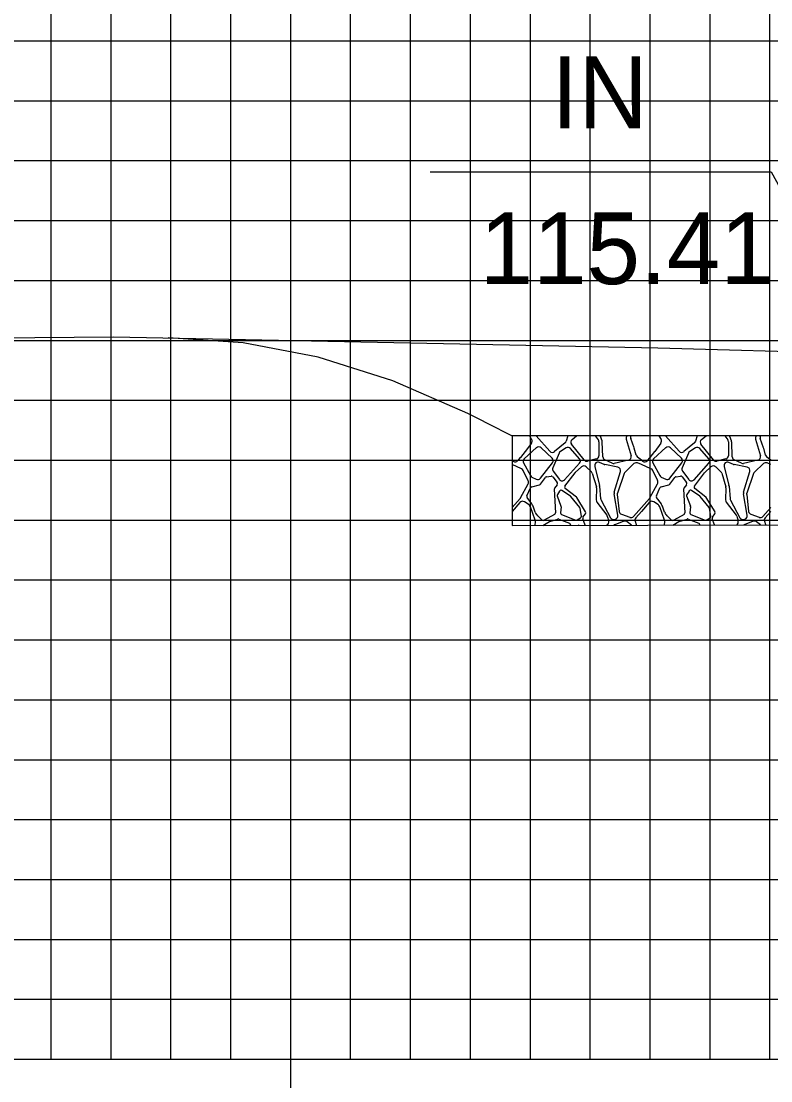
# Model space of a CAD drawing. Extents: x 1771629 to 1771972, y 442591 to 442811.
# Drawn here: x 1771740.08 to 1771752.59, y 442608.3 to 442625.99 of the extents above; entities that cross this region are included whole.
import ezdxf

# ---------------------------------------------------------------- set-up
doc = ezdxf.new("R2010")
doc.units = 0
for name, color, linetype in [('ANNOTATION', 7, 'Continuous'), ('D_Roadway_SlopeLines', 7, 'Continuous'), ('MAJOR', 7, 'Continuous'), ('MINOR', 7, 'Continuous'), ('S_Roadway_Centerline', 7, 'Continuous')]:
    doc.layers.add(name, color=color, linetype=linetype)

msp = doc.modelspace()

# ---------------------------------------------------------------- linework, layer by layer
at = {"layer": 'ANNOTATION'}
msp.add_lwpolyline([(1771746.908, 442623.478), (1771752.6, 442623.478), (1771755.024, 442619.074)], dxfattribs=at)
at = {"layer": 'D_Roadway_SlopeLines'}
for p, q in [((1771748.076, 442619.173), (1771748.274, 442619.074)), ((1771748.599, 442618.95), (1771748.496, 442618.811)), ((1771748.566, 442619.074), (1771748.602, 442619.012)), ((1771748.906, 442618.814), (1771748.678, 442619.074)), ((1771749.162, 442618.956), (1771748.985, 442618.808)), ((1771749.204, 442619.074), (1771749.18, 442618.985)), ((1771749.477, 442618.669), (1771749.269, 442618.932)), ((1771749.277, 442619.011), (1771749.353, 442619.074)), ((1771749.665, 442619.074), (1771749.715, 442619.006)), ((1771749.726, 442618.973), (1771749.726, 442618.74)), ((1771749.777, 442618.988), (1771749.753, 442619.058)), ((1771749.791, 442618.719), (1771749.78, 442618.971)), ((1771750.189, 442619.074), (1771750.181, 442619.046)), ((1771750.181, 442619.015), (1771750.261, 442618.736)), ((1771750.255, 442619.058), (1771750.258, 442619.074)), ((1771750.315, 442618.869), (1771750.257, 442619.029)), ((1771750.759, 442618.95), (1771750.656, 442618.811)), ((1771750.726, 442619.074), (1771750.762, 442619.012)), ((1771751.066, 442618.814), (1771750.838, 442619.074)), ((1771751.322, 442618.956), (1771751.145, 442618.808)), ((1771751.364, 442619.074), (1771751.34, 442618.985)), ((1771751.637, 442618.669), (1771751.429, 442618.932)), ((1771751.437, 442619.011), (1771751.513, 442619.074)), ((1771751.825, 442619.074), (1771751.875, 442619.006)), ((1771751.886, 442618.973), (1771751.886, 442618.74)), ((1771751.937, 442618.988), (1771751.913, 442619.058)), ((1771751.951, 442618.719), (1771751.941, 442618.971)), ((1771752.349, 442619.074), (1771752.341, 442619.046)), ((1771752.341, 442619.015), (1771752.421, 442618.736)), ((1771752.415, 442619.058), (1771752.418, 442619.074)), ((1771752.475, 442618.869), (1771752.418, 442619.029)), ((1771748.495, 442618.809), (1771748.414, 442618.709)), ((1771748.683, 442618.874), (1771748.477, 442618.689)), ((1771748.943, 442618.698), (1771748.76, 442618.872)), ((1771749.059, 442618.782), (1771748.955, 442618.538)), ((1771749.177, 442618.87), (1771749.081, 442618.808)), ((1771749.401, 442618.688), (1771749.251, 442618.86)), ((1771750.348, 442618.746), (1771750.316, 442618.864)), ((1771750.655, 442618.809), (1771750.574, 442618.709)), ((1771750.843, 442618.874), (1771750.637, 442618.689)), ((1771751.103, 442618.698), (1771750.92, 442618.872)), ((1771751.219, 442618.782), (1771751.115, 442618.538)), ((1771751.337, 442618.87), (1771751.241, 442618.808)), ((1771751.561, 442618.688), (1771751.411, 442618.86)), ((1771752.508, 442618.746), (1771752.476, 442618.864)), ((1771748.293, 442618.649), (1771748.274, 442618.665)), ((1771748.434, 442618.522), (1771748.274, 442618.591)), ((1771748.413, 442618.709), (1771748.373, 442618.659)), ((1771748.465, 442618.619), (1771748.581, 442618.407)), ((1771748.751, 442618.362), (1771748.949, 442618.622)), ((1771749.153, 442618.339), (1771749.4, 442618.613)), ((1771749.682, 442618.685), (1771749.535, 442618.649)), ((1771749.813, 442618.595), (1771749.733, 442618.628)), ((1771750.04, 442618.548), (1771749.823, 442618.591)), ((1771749.946, 442618.616), (1771749.825, 442618.67)), ((1771750.218, 442618.665), (1771749.981, 442618.612)), ((1771750.309, 442618.607), (1771750.162, 442618.467)), ((1771750.434, 442618.665), (1771750.368, 442618.716)), ((1771750.434, 442618.591), (1771750.371, 442618.618)), ((1771750.454, 442618.649), (1771750.434, 442618.665)), ((1771750.594, 442618.522), (1771750.434, 442618.591)), ((1771750.573, 442618.709), (1771750.533, 442618.659)), ((1771750.625, 442618.619), (1771750.741, 442618.407)), ((1771750.911, 442618.362), (1771751.109, 442618.622)), ((1771751.313, 442618.339), (1771751.561, 442618.613)), ((1771751.842, 442618.685), (1771751.695, 442618.649)), ((1771751.973, 442618.595), (1771751.893, 442618.628)), ((1771752.2, 442618.548), (1771751.983, 442618.591)), ((1771752.106, 442618.616), (1771751.985, 442618.67)), ((1771752.379, 442618.665), (1771752.141, 442618.612)), ((1771752.47, 442618.607), (1771752.322, 442618.467)), ((1771752.594, 442618.665), (1771752.528, 442618.716)), ((1771752.594, 442618.591), (1771752.531, 442618.618)), ((1771748.546, 442618.32), (1771748.463, 442618.494)), ((1771748.852, 442618.388), (1771748.926, 442618.4)), ((1771748.953, 442618.389), (1771749.028, 442618.29)), ((1771748.962, 442618.481), (1771749.065, 442618.343)), ((1771749.158, 442618.231), (1771749.328, 442618.453)), ((1771749.331, 442618.457), (1771749.435, 442618.553)), ((1771749.513, 442618.553), (1771749.599, 442618.471)), ((1771749.614, 442618.446), (1771749.683, 442618.22)), ((1771749.656, 442618.561), (1771749.735, 442618.241)), ((1771749.979, 442618.13), (1771750.083, 442618.476)), ((1771750.147, 442618.444), (1771750.034, 442618.117)), ((1771750.706, 442618.32), (1771750.623, 442618.494)), ((1771751.012, 442618.388), (1771751.086, 442618.4)), ((1771751.113, 442618.389), (1771751.188, 442618.29)), ((1771751.122, 442618.481), (1771751.225, 442618.343)), ((1771751.318, 442618.231), (1771751.488, 442618.453)), ((1771751.491, 442618.457), (1771751.595, 442618.553)), ((1771751.674, 442618.553), (1771751.759, 442618.471)), ((1771751.775, 442618.446), (1771751.843, 442618.22)), ((1771751.816, 442618.561), (1771751.895, 442618.241)), ((1771752.139, 442618.13), (1771752.243, 442618.476)), ((1771752.307, 442618.444), (1771752.194, 442618.117)), ((1771748.417, 442618.035), (1771748.544, 442618.268)), ((1771748.603, 442618.221), (1771748.734, 442618.253)), ((1771748.606, 442618.383), (1771748.68, 442618.346)), ((1771748.75, 442618.264), (1771748.833, 442618.377)), ((1771749.028, 442618.256), (1771748.985, 442618.199)), ((1771749.736, 442618.232), (1771749.754, 442618.022)), ((1771750.577, 442618.035), (1771750.704, 442618.268)), ((1771750.764, 442618.221), (1771750.894, 442618.253)), ((1771750.766, 442618.383), (1771750.84, 442618.346)), ((1771750.91, 442618.264), (1771750.993, 442618.377)), ((1771751.188, 442618.256), (1771751.145, 442618.199)), ((1771751.897, 442618.232), (1771751.914, 442618.022)), ((1771748.524, 442618.069), (1771748.584, 442618.205)), ((1771748.606, 442617.935), (1771748.527, 442618.041)), ((1771748.979, 442618.181), (1771749, 442617.787)), ((1771749.028, 442618.069), (1771749.091, 442617.9)), ((1771749.068, 442618.15), (1771749.031, 442618.094)), ((1771749.251, 442618.063), (1771749.108, 442618.158)), ((1771749.351, 442618.048), (1771749.163, 442618.191)), ((1771749.404, 442617.874), (1771749.257, 442618.057)), ((1771749.503, 442617.803), (1771749.358, 442618.04)), ((1771749.685, 442618.202), (1771749.68, 442618.002)), ((1771750.042, 442617.746), (1771749.978, 442618.104)), ((1771750.031, 442618.092), (1771750.064, 442617.809)), ((1771750.684, 442618.069), (1771750.744, 442618.205)), ((1771750.767, 442617.935), (1771750.687, 442618.041)), ((1771751.139, 442618.181), (1771751.16, 442617.787)), ((1771751.188, 442618.069), (1771751.251, 442617.9)), ((1771751.229, 442618.15), (1771751.191, 442618.094)), ((1771751.411, 442618.063), (1771751.268, 442618.158)), ((1771751.511, 442618.048), (1771751.324, 442618.191)), ((1771751.564, 442617.874), (1771751.417, 442618.057)), ((1771751.663, 442617.803), (1771751.518, 442618.04)), ((1771751.845, 442618.202), (1771751.84, 442618.002)), ((1771752.202, 442617.746), (1771752.138, 442618.104)), ((1771752.192, 442618.092), (1771752.224, 442617.809)), ((1771748.274, 442617.873), (1771748.409, 442618.024)), ((1771748.406, 442617.96), (1771748.274, 442617.809)), ((1771748.559, 442617.917), (1771748.48, 442617.969)), ((1771748.661, 442617.665), (1771748.58, 442617.889)), ((1771748.662, 442617.797), (1771748.627, 442617.896)), ((1771749.093, 442617.887), (1771749.083, 442617.786)), ((1771749.433, 442617.73), (1771749.41, 442617.861)), ((1771749.691, 442617.966), (1771749.856, 442617.747)), ((1771749.76, 442618), (1771749.916, 442617.704)), ((1771750.303, 442617.726), (1771750.434, 442617.873)), ((1771750.434, 442617.873), (1771750.569, 442618.024)), ((1771750.566, 442617.96), (1771750.434, 442617.809)), ((1771750.719, 442617.917), (1771750.641, 442617.969)), ((1771750.822, 442617.665), (1771750.741, 442617.889)), ((1771750.822, 442617.797), (1771750.787, 442617.896)), ((1771751.253, 442617.887), (1771751.243, 442617.786)), ((1771751.593, 442617.73), (1771751.57, 442617.861)), ((1771751.851, 442617.966), (1771752.016, 442617.747)), ((1771751.92, 442618), (1771752.076, 442617.704)), ((1771752.464, 442617.726), (1771752.594, 442617.873)), ((1771748.779, 442617.665), (1771748.7, 442617.739)), ((1771748.986, 442617.76), (1771748.813, 442617.661)), ((1771748.905, 442617.643), (1771749.037, 442617.683)), ((1771749.056, 442617.682), (1771749.233, 442617.611)), ((1771749.101, 442617.757), (1771749.339, 442617.665)), ((1771749.364, 442617.668), (1771749.42, 442617.701)), ((1771749.496, 442617.578), (1771749.455, 442617.684)), ((1771749.458, 442617.711), (1771749.501, 442617.771)), ((1771749.865, 442617.73), (1771749.89, 442617.65)), ((1771749.982, 442617.676), (1771750.001, 442617.681)), ((1771750.101, 442617.762), (1771750.241, 442617.711)), ((1771750.434, 442617.809), (1771750.339, 442617.7)), ((1771750.939, 442617.665), (1771750.86, 442617.739)), ((1771751.146, 442617.76), (1771750.973, 442617.661)), ((1771751.065, 442617.643), (1771751.197, 442617.683)), ((1771751.216, 442617.682), (1771751.393, 442617.611)), ((1771751.261, 442617.757), (1771751.499, 442617.665)), ((1771751.524, 442617.668), (1771751.58, 442617.701)), ((1771751.654, 442617.584), (1771751.615, 442617.684)), ((1771751.619, 442617.711), (1771751.662, 442617.771)), ((1771752.025, 442617.73), (1771752.05, 442617.65)), ((1771752.142, 442617.676), (1771752.161, 442617.681)), ((1771752.261, 442617.762), (1771752.402, 442617.711)), ((1771752.594, 442617.809), (1771752.499, 442617.7)), ((1771748.661, 442617.575), (1771748.665, 442617.643)), ((1771748.789, 442617.576), (1771748.899, 442617.64)), ((1771749.25, 442617.584), (1771749.25, 442617.577)), ((1771749.854, 442617.579), (1771749.853, 442617.579)), ((1771750.141, 442617.646), (1771749.989, 442617.588)), ((1771750.271, 442617.58), (1771750.196, 442617.638)), ((1771750.328, 442617.646), (1771750.344, 442617.592)), ((1771750.821, 442617.581), (1771750.825, 442617.643)), ((1771750.96, 442617.582), (1771751.059, 442617.64)), ((1771751.411, 442617.584), (1771751.411, 442617.583)), ((1771752.301, 442617.646), (1771752.149, 442617.588)), ((1771752.423, 442617.586), (1771752.356, 442617.638)), ((1771752.488, 442617.646), (1771752.504, 442617.592))]:
    msp.add_line(p, q, dxfattribs=at)
for points in [[(1771748.076, 442619.173), (1771747.536, 442619.443), (1771746.286, 442619.991), (1771745.036, 442620.384), (1771743.786, 442620.622), (1771742.536, 442620.706)], [(1771755.024, 442619.074), (1771748.274, 442619.074), (1771748.274, 442617.574), (1771755.074, 442617.594)]]:
    msp.add_lwpolyline(points, dxfattribs=at)
for centre, radius, start, end in [((1771748.553, 442618.983), 0.057, 323.4711, 30.6507), ((1771749.125, 442618.999), 0.057, 309.9575, 345.2564), ((1771749.313, 442618.967), 0.057, 129.4712, 218.373), ((1771749.669, 442618.973), 0.057, 0.0888, 36.2192), ((1771749.806, 442619.077), 0.057, 182.6788, 199.44), ((1771749.723, 442618.969), 0.057, 2.4366, 19.44), ((1771750.236, 442619.03), 0.057, 164.0546, 195.9454), ((1771750.311, 442619.048), 0.057, 170.1342, 199.6538), ((1771750.713, 442618.983), 0.057, 323.4711, 30.6507), ((1771751.285, 442618.999), 0.057, 309.9575, 345.2564), ((1771751.473, 442618.967), 0.057, 129.4712, 218.373), ((1771751.829, 442618.973), 0.057, 0.0888, 36.2192), ((1771751.967, 442619.077), 0.057, 182.6788, 199.44), ((1771751.884, 442618.969), 0.057, 2.4366, 19.44), ((1771752.396, 442619.03), 0.057, 164.0546, 195.9454), ((1771752.471, 442619.048), 0.057, 170.1342, 199.6538), ((1771748.45, 442618.845), 0.057, 320.9061, 323.4711), ((1771748.721, 442618.831), 0.057, 46.4321, 131.8334), ((1771748.949, 442618.852), 0.057, 221.257, 309.9575), ((1771749.112, 442618.76), 0.057, 122.9625, 156.9778), ((1771749.208, 442618.822), 0.057, 41.2462, 122.9625), ((1771749.669, 442618.74), 0.057, 283.5819, 0.0888), ((1771750.261, 442618.849), 0.057, 15.2551, 19.6538), ((1771750.403, 442618.761), 0.057, 195.2551, 231.953), ((1771750.61, 442618.845), 0.057, 320.9061, 323.4711), ((1771750.881, 442618.831), 0.057, 46.4321, 131.8334), ((1771751.109, 442618.852), 0.057, 221.257, 309.9575), ((1771751.272, 442618.76), 0.057, 122.9625, 156.9778), ((1771751.368, 442618.822), 0.057, 41.2462, 122.9625), ((1771751.829, 442618.74), 0.057, 283.5819, 0.0888), ((1771752.421, 442618.849), 0.057, 15.2551, 19.6538), ((1771752.563, 442618.761), 0.057, 195.2551, 231.953), ((1771748.329, 442618.694), 0.057, 231.953, 321.3402), ((1771748.458, 442618.673), 0.057, 140.9061, 141.3402), ((1771748.515, 442618.646), 0.057, 131.8334, 208.7575), ((1771748.904, 442618.657), 0.057, 322.6367, 46.4321), ((1771749.358, 442618.651), 0.057, 317.8776, 41.2462), ((1771749.474, 442618.511), 0.057, 46.3639, 132.7891), ((1771749.521, 442618.704), 0.057, 218.373, 283.5819), ((1771749.711, 442618.575), 0.057, 67.4775, 193.8595), ((1771749.848, 442618.722), 0.057, 182.4366, 246.0375), ((1771749.834, 442618.647), 0.057, 247.4775, 258.7067), ((1771749.969, 442618.668), 0.057, 246.0375, 282.4074), ((1771750.206, 442618.72), 0.057, 282.4074, 15.9454), ((1771750.349, 442618.566), 0.057, 66.6444, 133.5732), ((1771750.489, 442618.694), 0.057, 231.953, 321.3402), ((1771750.618, 442618.673), 0.057, 140.9061, 141.3402), ((1771750.675, 442618.646), 0.057, 131.8334, 208.7575), ((1771751.064, 442618.657), 0.057, 322.6367, 46.4321), ((1771751.518, 442618.651), 0.057, 317.8776, 41.2462), ((1771751.634, 442618.511), 0.057, 46.3639, 132.7891), ((1771751.682, 442618.704), 0.057, 218.373, 283.5819), ((1771751.871, 442618.575), 0.057, 67.4775, 193.8595), ((1771752.008, 442618.722), 0.057, 182.4366, 246.0375), ((1771751.995, 442618.647), 0.057, 247.4775, 258.7067), ((1771752.129, 442618.668), 0.057, 246.0375, 282.4074), ((1771752.366, 442618.72), 0.057, 282.4074, 15.9454), ((1771752.509, 442618.566), 0.057, 66.6444, 133.5732), ((1771748.411, 442618.47), 0.057, 25.4039, 66.6444), ((1771748.631, 442618.434), 0.057, 208.7575, 243.4931), ((1771748.856, 442618.36), 0.0285, 98.7462, 143.6864), ((1771748.93, 442618.371), 0.0285, 37.5348, 98.7462), ((1771749.008, 442618.515), 0.057, 156.9778, 216.6071), ((1771749.351, 442618.436), 0.0285, 132.7891, 142.5946), ((1771749.56, 442618.429), 0.057, 16.8986, 46.3639), ((1771750.029, 442618.492), 0.057, 343.267, 78.7067), ((1771750.201, 442618.425), 0.057, 133.5732, 160.9362), ((1771750.572, 442618.47), 0.057, 25.4039, 66.6444), ((1771750.791, 442618.434), 0.057, 208.7575, 243.4931), ((1771751.016, 442618.36), 0.0285, 98.7462, 143.6864), ((1771751.09, 442618.371), 0.0285, 37.5348, 98.7462), ((1771751.168, 442618.515), 0.057, 156.9778, 216.6071), ((1771751.511, 442618.436), 0.0285, 132.7891, 142.5946), ((1771751.72, 442618.429), 0.057, 16.8986, 46.3639), ((1771752.189, 442618.492), 0.057, 343.267, 78.7067), ((1771752.361, 442618.425), 0.057, 133.5732, 160.9362), ((1771748.494, 442618.295), 0.057, 331.294, 25.4039), ((1771748.61, 442618.194), 0.0285, 103.7608, 156.1398), ((1771748.705, 442618.397), 0.057, 243.4931, 322.6367), ((1771748.727, 442618.281), 0.0285, 283.7608, 323.6864), ((1771749.006, 442618.273), 0.0285, 322.4314, 37.5348), ((1771749.111, 442618.377), 0.057, 216.6071, 317.8776), ((1771749.181, 442618.214), 0.0285, 142.5946, 232.5946), ((1771749.628, 442618.204), 0.057, 358.4306, 16.8986), ((1771749.68, 442618.228), 0.057, 4.7636, 13.8595), ((1771750.654, 442618.295), 0.057, 331.294, 25.4039), ((1771750.77, 442618.194), 0.0285, 103.7608, 156.1398), ((1771750.865, 442618.397), 0.057, 243.4931, 322.6367), ((1771750.887, 442618.281), 0.0285, 283.7608, 323.6864), ((1771751.166, 442618.273), 0.0285, 322.4314, 37.5348), ((1771751.271, 442618.377), 0.057, 216.6071, 317.8776), ((1771751.341, 442618.214), 0.0285, 142.5946, 232.5946), ((1771751.789, 442618.204), 0.057, 358.4306, 16.8986), ((1771751.84, 442618.228), 0.057, 4.7636, 13.8595), ((1771748.367, 442618.062), 0.057, 318.2412, 331.294), ((1771748.55, 442618.058), 0.0285, 156.1398, 216.7644), ((1771749.008, 442618.182), 0.0285, 142.4314, 182.9903), ((1771749.055, 442618.079), 0.0285, 146.3099, 200.4835), ((1771749.092, 442618.134), 0.0285, 56.3099, 146.3099), ((1771749.235, 442618.039), 0.0285, 38.7742, 56.3099), ((1771749.333, 442618.025), 0.0285, 31.373, 52.5946), ((1771750.034, 442618.114), 0.057, 163.267, 190.1543), ((1771750.088, 442618.099), 0.057, 160.9362, 186.5245), ((1771750.527, 442618.062), 0.057, 318.2412, 331.294), ((1771750.71, 442618.058), 0.0285, 156.1398, 216.7644), ((1771751.168, 442618.182), 0.0285, 142.4314, 182.9903), ((1771751.215, 442618.079), 0.0285, 146.3099, 200.4835), ((1771751.252, 442618.134), 0.0285, 56.3099, 146.3099), ((1771751.395, 442618.039), 0.0285, 38.7742, 56.3099), ((1771751.494, 442618.025), 0.0285, 31.373, 52.5946), ((1771752.194, 442618.114), 0.057, 163.267, 190.1543), ((1771752.248, 442618.099), 0.057, 160.9362, 186.5245), ((1771748.449, 442617.922), 0.057, 56.0035, 138.8937), ((1771748.527, 442617.869), 0.057, 19.9256, 56.0035), ((1771748.492, 442617.85), 0.142, 19.1336, 36.7644), ((1771749.065, 442617.89), 0.0285, 354.4278, 20.4835), ((1771749.382, 442617.856), 0.0285, 10.204, 38.7742), ((1771749.737, 442618), 0.057, 178.4306, 216.9888), ((1771749.811, 442618.026), 0.057, 184.7636, 207.8015), ((1771750.609, 442617.922), 0.057, 56.0035, 138.8937), ((1771750.687, 442617.869), 0.057, 19.9256, 56.0035), ((1771750.652, 442617.85), 0.142, 19.1336, 36.7644), ((1771751.225, 442617.89), 0.0285, 354.4278, 20.4835), ((1771751.542, 442617.856), 0.0285, 10.204, 38.7742), ((1771751.897, 442618), 0.057, 178.4306, 216.9888), ((1771751.971, 442618.026), 0.057, 184.7636, 207.8015), ((1771748.796, 442617.843), 0.142, 199.1336, 227.3215), ((1771748.971, 442617.785), 0.0285, 299.792, 2.9903), ((1771749.045, 442617.656), 0.0285, 68.1986, 106.9275), ((1771749.111, 442617.783), 0.0285, 174.4278, 249.0071), ((1771749.405, 442617.725), 0.0285, 300.6507, 10.204), ((1771749.482, 442617.694), 0.0285, 144.4623, 201.1941), ((1771749.478, 442617.788), 0.0285, 324.4623, 31.373), ((1771749.81, 442617.713), 0.057, 17.2815, 36.9888), ((1771749.967, 442617.731), 0.057, 207.8015, 285.5241), ((1771749.986, 442617.736), 0.057, 285.5241, 10.1543), ((1771750.12, 442617.815), 0.057, 186.5245, 250.0795), ((1771750.261, 442617.764), 0.057, 250.0795, 318.2412), ((1771750.382, 442617.663), 0.057, 138.8937, 196.8584), ((1771750.956, 442617.843), 0.142, 199.1336, 227.3215), ((1771751.131, 442617.785), 0.0285, 299.792, 2.9903), ((1771751.205, 442617.656), 0.0285, 68.1986, 106.9275), ((1771751.272, 442617.783), 0.0285, 174.4278, 249.0071), ((1771751.565, 442617.725), 0.0285, 300.6507, 10.204), ((1771751.642, 442617.694), 0.0285, 144.4623, 201.1941), ((1771751.638, 442617.788), 0.0285, 324.4623, 31.373), ((1771751.971, 442617.713), 0.057, 17.2815, 36.9888), ((1771752.127, 442617.731), 0.057, 207.8015, 285.5241), ((1771752.146, 442617.736), 0.057, 285.5241, 10.1543), ((1771752.281, 442617.815), 0.057, 186.5245, 250.0795), ((1771752.421, 442617.764), 0.057, 250.0795, 318.2412), ((1771752.542, 442617.663), 0.057, 138.8937, 196.8584), ((1771748.608, 442617.646), 0.057, 356.7755, 19.9256), ((1771748.798, 442617.686), 0.0285, 227.3215, 299.792), ((1771748.913, 442617.615), 0.0285, 106.9275, 120.5102), ((1771749.222, 442617.585), 0.0285, 358.1221, 68.1986), ((1771749.349, 442617.692), 0.0285, 249.0071, 300.6507), ((1771749.387, 442617.521), 0.057, 81.0945, 99.2406), ((1771749.835, 442617.633), 0.057, 289.5367, 17.2815), ((1771750.009, 442617.535), 0.057, 110.9245, 128.9181), ((1771750.161, 442617.593), 0.057, 52.2243, 110.9245), ((1771750.399, 442617.608), 0.057, 196.8584, 209.5096), ((1771750.768, 442617.646), 0.057, 356.7755, 19.9256), ((1771750.959, 442617.686), 0.0285, 227.3215, 299.792), ((1771751.073, 442617.615), 0.0285, 106.9275, 120.5102), ((1771751.382, 442617.585), 0.0285, 358.1221, 68.1986), ((1771751.509, 442617.692), 0.0285, 249.0071, 300.6507), ((1771751.995, 442617.633), 0.057, 302.7284, 17.2815), ((1771752.169, 442617.535), 0.057, 110.9245, 117.2024), ((1771752.321, 442617.593), 0.057, 52.2243, 110.9245), ((1771752.559, 442617.608), 0.057, 196.8584, 202.4499)]:
    msp.add_arc(centre, radius, start, end, dxfattribs=at)
at = {"layer": 'MAJOR'}
for p, q in [((1771744.58, 442608.665), (1771744.58, 442633.665)), ((1771654.58, 442623.665), (1771934.58, 442623.665)), ((1771654.58, 442618.665), (1771934.58, 442618.665)), ((1771654.58, 442613.665), (1771934.58, 442613.665)), ((1771654.58, 442608.665), (1771934.58, 442608.665)), ((1771654.58, 442608.665), (1771934.58, 442608.665)), ((1771744.58, 442606.661), (1771744.58, 442608.665))]:
    msp.add_line(p, q, dxfattribs=at)
at = {"layer": 'MINOR'}
for p, q in [((1771740.58, 442608.665), (1771740.58, 442633.665)), ((1771741.58, 442608.665), (1771741.58, 442633.665)), ((1771742.58, 442608.665), (1771742.58, 442633.665)), ((1771743.58, 442608.665), (1771743.58, 442633.665)), ((1771745.58, 442608.665), (1771745.58, 442633.665)), ((1771746.58, 442608.665), (1771746.58, 442633.665)), ((1771747.58, 442608.665), (1771747.58, 442633.665)), ((1771748.58, 442608.665), (1771748.58, 442633.665)), ((1771749.58, 442608.665), (1771749.58, 442633.665)), ((1771750.58, 442608.665), (1771750.58, 442633.665)), ((1771751.58, 442608.665), (1771751.58, 442633.665)), ((1771752.58, 442608.665), (1771752.58, 442633.665)), ((1771654.58, 442625.665), (1771934.58, 442625.665)), ((1771654.58, 442624.665), (1771934.58, 442624.665)), ((1771654.58, 442622.665), (1771934.58, 442622.665)), ((1771654.58, 442621.665), (1771934.58, 442621.665)), ((1771654.58, 442620.665), (1771934.58, 442620.665)), ((1771654.58, 442619.665), (1771934.58, 442619.665)), ((1771654.58, 442617.665), (1771934.58, 442617.665)), ((1771654.58, 442616.665), (1771934.58, 442616.665)), ((1771654.58, 442615.665), (1771934.58, 442615.665)), ((1771654.58, 442614.665), (1771934.58, 442614.665)), ((1771654.58, 442612.665), (1771934.58, 442612.665)), ((1771654.58, 442611.665), (1771934.58, 442611.665)), ((1771654.58, 442610.665), (1771934.58, 442610.665)), ((1771654.58, 442609.665), (1771934.58, 442609.665))]:
    msp.add_line(p, q, dxfattribs=at)
at = {"layer": 'S_Roadway_Centerline'}
msp.add_lwpolyline([(1771735.693, 442620.673), (1771741.62, 442620.724), (1771750.71, 442620.542), (1771753.896, 442620.449), (1771755.85, 442620.471), (1771771.303, 442620.344), (1771776.843, 442620.306), (1771777.606, 442620.288), (1771778.581, 442620.28), (1771796.912, 442619.652), (1771806.41, 442619.413), (1771816.58, 442619.351), (1771823.837, 442619.187), (1771834.719, 442618.832), (1771836.337, 442618.77), (1771837.241, 442618.711), (1771847.903, 442618.211), (1771857.287, 442617.889)], dxfattribs=at)

# ---------------------------------------------------------------- texts
at = {"layer": 'ANNOTATION'}
for s, p in [('IN', (1771748.935, 442624.204)), ('115.41', (1771747.734, 442621.604))]:
    msp.add_text(s, height=1.2, dxfattribs=at).set_placement(p)

doc.saveas('drawing.dxf')
